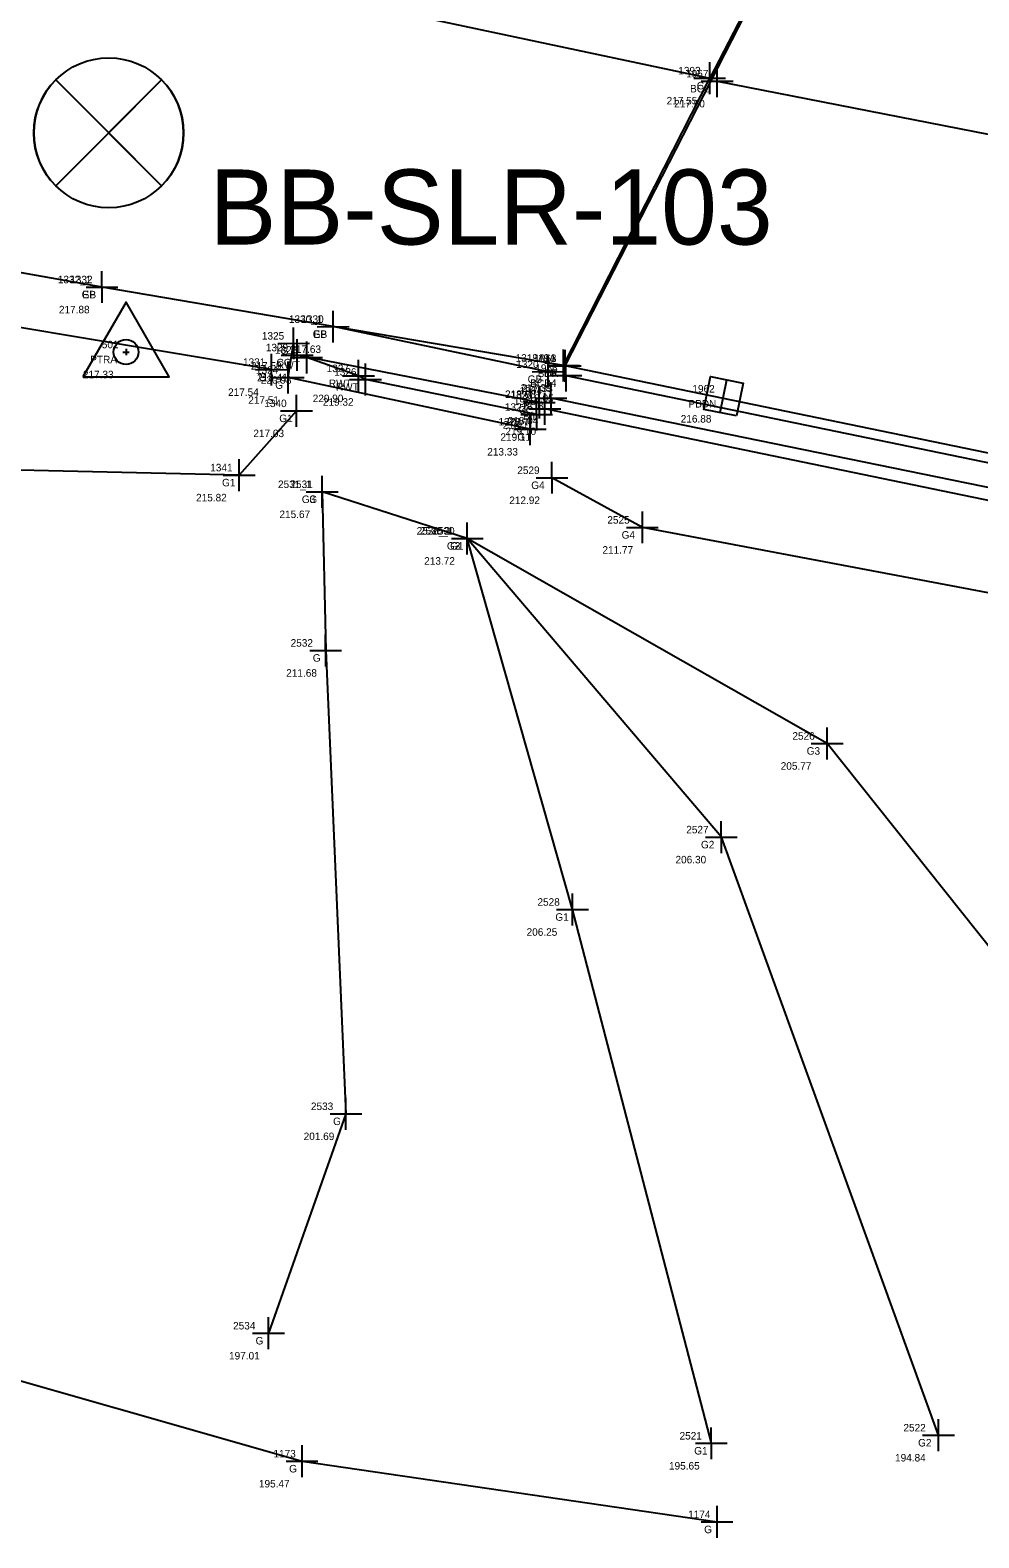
# Model space of a CAD drawing. Extents: x 1155460 to 1157069, y 590691 to 591363.
# Drawn here: x 1156288 to 1156326, y 591043.2 to 591103.4 of the extents above; entities that cross this region are included whole.
import ezdxf

# ---------------------------------------------------------------- set-up
doc = ezdxf.new("R2010")
doc.units = 0
for name, color, linetype in [('Default', 7, 'Continuous'), ('S_BoringLocation_AsDrilled', 7, 'Continuous'), ('S_Bridge_Centerline', 7, 'Continuous'), ('S_Bridge_Curb', 7, 'Continuous'), ('S_Bridge_Deck', 7, 'Continuous'), ('S_Bridge_Downspout', 7, 'Continuous'), ('S_Bridge_Rail', 7, 'Continuous'), ('S_Control_Traverse_Point', 7, 'Continuous'), ('S_Curb_Type_2', 7, 'Continuous'), ('S_Field_Code', 7, 'Continuous'), ('S_Ground_Elevation', 7, 'Continuous'), ('S_Ground_LevelString', 7, 'Continuous'), ('S_Guardrail_Beam', 7, 'Continuous'), ('S_Point_Elevation', 7, 'Continuous'), ('S_Point_Name', 7, 'Continuous'), ('S_RetWall_Top', 7, 'Continuous'), ('S_Roadway_Centerline', 7, 'Continuous'), ('S_Roadway_Edge_Pavement', 7, 'Continuous'), ('S_Survey_Shot', 7, 'Continuous'), ('S_Text', 7, 'Continuous')]:
    doc.layers.add(name, color=color, linetype=linetype)

msp = doc.modelspace()

# ---------------------------------------------------------------- linework, layer by layer
at = {"layer": 'Default'}
for p, q in [((1156291.176, 591099.304), (1156291.176, 591099.304)), ((1156315.757, 591088.777), (1156315.757, 591088.777))]:
    msp.add_line(p, q, dxfattribs=at)
at = {"layer": 'S_BoringLocation_AsDrilled'}
for p, q in [((1156289.059, 591101.422), (1156293.293, 591097.187)), ((1156289.059, 591097.187), (1156293.293, 591101.422))]:
    msp.add_line(p, q, dxfattribs=at)
for points in [[(1156289.059, 591097.187), (1156291.176, 591099.304), (1156289.059, 591101.422)], [(1156293.293, 591101.422), (1156291.176, 591099.304), (1156293.293, 591097.187)]]:
    msp.add_lwpolyline(points, dxfattribs=at)
msp.add_circle((1156291.176, 591099.304), 2.994, dxfattribs=at)
for start, end in [(135, 225), (315, 45)]:
    msp.add_arc((1156291.176, 591099.304), 2.994, start, end, dxfattribs=at)
at = {"layer": 'S_Bridge_Centerline'}
msp.add_lwpolyline([(1156315.508, 591101.371), (1156372.408, 591090.24), (1156431.554, 591078.114), (1156475.254, 591069.515)], dxfattribs=at)
at = {"layer": 'S_Bridge_Curb'}
for points in [[(1156309.461, 591089.603), (1156368.986, 591077.329), (1156424.735, 591065.932), (1156469.272, 591056.957)], [(1156468.917, 591055.972), (1156425.26, 591064.917), (1156366.557, 591076.907), (1156308.862, 591088.698)]]:
    msp.add_lwpolyline(points, dxfattribs=at)
at = {"layer": 'S_Bridge_Deck'}
msp.add_lwpolyline([(1156321.636, 591113.83), (1156379.075, 591102.191), (1156438.058, 591090.105), (1156481.699, 591081.221), (1156469.523, 591057.135), (1156425.816, 591065.905), (1156367.048, 591078.105), (1156309.431, 591089.995)], close=True, dxfattribs=at)
at = {"layer": 'S_Bridge_Downspout'}
msp.add_line((1156315.626, 591088.124), (1156315.888, 591089.431), dxfattribs=at)
msp.add_lwpolyline([(1156316.28, 591087.993), (1156314.973, 591088.254), (1156315.234, 591089.562), (1156316.541, 591089.3)], close=True, dxfattribs=at)
at = {"layer": 'S_Bridge_Rail'}
msp.add_lwpolyline([(1156468.705, 591055.401), (1156424.96, 591064.338), (1156366.256, 591076.365), (1156308.616, 591088.276)], dxfattribs=at)
at = {"layer": 'S_Control_Traverse_Point'}
for p, q in [((1156291.744, 591090.546), (1156291.994, 591090.546)), ((1156291.869, 591090.67), (1156291.869, 591090.421))]:
    msp.add_line(p, q, dxfattribs=at)
msp.add_lwpolyline([(1156290.14, 591089.548), (1156293.598, 591089.548), (1156291.869, 591092.542)], close=True, dxfattribs=at)
msp.add_circle((1156291.869, 591090.546), 0.499, dxfattribs=at)
at = {"layer": 'S_Curb_Type_2'}
msp.add_lwpolyline([(1156308.396, 591088.531), (1156298.714, 591090.424)], dxfattribs=at)
at = {"layer": 'S_Ground_Elevation'}
for points in [[(1156297.688, 591089.841), (1156262.191, 591095.758), (1156236.062, 591101.394), (1156225.846, 591104.279)], [(1156298.682, 591088.195), (1156296.392, 591085.627), (1156279.978, 591085.999), (1156263.481, 591092.536), (1156249.725, 591093.66), (1156229.629, 591098.08), (1156224.845, 591100.347), (1156224.904, 591103.352)], [(1156175.788, 591102.575), (1156176.723, 591093.187), (1156183.705, 591081.742), (1156199.952, 591071.527), (1156234.308, 591066.18), (1156269.105, 591054.717), (1156298.907, 591046.22), (1156315.501, 591043.792)], [(1156308.034, 591087.459), (1156298.35, 591089.525), (1156298.572, 591090.892)], [(1156353.701, 591075.748), (1156312.515, 591083.537), (1156308.901, 591085.521)], [(1156299.714, 591084.96), (1156299.852, 591078.62), (1156300.662, 591060.102), (1156297.566, 591051.334)], [(1156336.683, 591053.85), (1156319.901, 591074.903), (1156305.515, 591083.097), (1156299.714, 591084.96)], [(1156315.273, 591046.935), (1156309.721, 591068.267), (1156305.515, 591083.097)], [(1156324.355, 591047.258), (1156315.673, 591071.16), (1156305.515, 591083.097)]]:
    msp.add_lwpolyline(points, dxfattribs=at)
at = {"layer": 'S_Ground_LevelString'}
msp.add_line((1156309.359, 591090.009), (1156309.359, 591090.009), dxfattribs=at)
for points in [[(1156321.612, 591113.838), (1156315.209, 591101.49)], [(1156309.359, 591090.009), (1156315.209, 591101.49)]]:
    msp.add_lwpolyline(points, dxfattribs=at)
at = {"layer": 'S_Guardrail_Beam'}
msp.add_lwpolyline([(1156308.743, 591089.76), (1156300.149, 591091.559), (1156290.91, 591093.141), (1156262.028, 591098.261), (1156236.884, 591103.703), (1156225.66, 591106.566), (1156223.814, 591107.26), (1156215.406, 591108.888)], dxfattribs=at)
at = {"layer": 'S_RetWall_Top'}
msp.add_lwpolyline([(1156308.287, 591088.047), (1156301.448, 591089.449), (1156301.165, 591089.592), (1156299.094, 591090.328)], dxfattribs=at)
at = {"layer": 'S_Roadway_Centerline'}
msp.add_lwpolyline([(1156220.901, 591120.629), (1156254.128, 591114.222), (1156297.601, 591105.231), (1156315.209, 591101.49)], dxfattribs=at)
at = {"layer": 'S_Roadway_Edge_Pavement'}
msp.add_lwpolyline([(1156309.359, 591090.009), (1156300.149, 591091.559), (1156290.91, 591093.141), (1156262.028, 591098.261), (1156236.884, 591103.703), (1156225.66, 591106.566), (1156223.814, 591107.26), (1156215.252, 591109.143)], dxfattribs=at)
at = {"layer": 'S_Survey_Shot'}
for p, q in [((1156315.21, 591100.854), (1156315.207, 591102.127)), ((1156315.51, 591100.735), (1156315.507, 591102.008)), ((1156314.573, 591101.489), (1156315.845, 591101.492)), ((1156314.872, 591101.37), (1156316.145, 591101.373)), ((1156315.209, 591101.49), (1156315.209, 591101.49)), ((1156315.508, 591101.371), (1156315.508, 591101.371)), ((1156290.911, 591092.505), (1156290.908, 591093.777)), ((1156290.911, 591092.505), (1156290.908, 591093.777)), ((1156290.274, 591093.14), (1156291.546, 591093.142)), ((1156290.274, 591093.14), (1156291.546, 591093.142)), ((1156290.91, 591093.141), (1156290.91, 591093.141)), ((1156290.91, 591093.141), (1156290.91, 591093.141)), ((1156300.15, 591090.922), (1156300.147, 591092.195)), ((1156300.15, 591090.922), (1156300.147, 591092.195)), ((1156298.573, 591090.255), (1156298.57, 591091.528)), ((1156299.512, 591091.557), (1156300.785, 591091.56)), ((1156299.512, 591091.557), (1156300.785, 591091.56)), ((1156300.149, 591091.559), (1156300.149, 591091.559)), ((1156300.149, 591091.559), (1156300.149, 591091.559)), ((1156297.935, 591090.89), (1156299.208, 591090.893)), ((1156298.572, 591090.892), (1156298.572, 591090.892)), ((1156298.715, 591089.788), (1156298.712, 591091.06)), ((1156299.095, 591089.692), (1156299.093, 591090.964)), ((1156297.689, 591089.205), (1156297.687, 591090.477)), ((1156298.078, 591090.423), (1156299.35, 591090.425)), ((1156298.352, 591088.889), (1156298.349, 591090.162)), ((1156298.458, 591090.327), (1156299.73, 591090.329)), ((1156298.714, 591090.424), (1156298.714, 591090.424)), ((1156299.094, 591090.328), (1156299.094, 591090.328)), ((1156301.167, 591088.956), (1156301.164, 591090.228)), ((1156308.744, 591089.124), (1156308.742, 591090.396)), ((1156309.36, 591089.373), (1156309.358, 591090.645)), ((1156309.36, 591089.373), (1156309.358, 591090.645)), ((1156309.432, 591089.358), (1156309.429, 591090.631)), ((1156309.463, 591088.966), (1156309.46, 591090.239)), ((1156297.052, 591089.84), (1156298.324, 591089.843)), ((1156297.688, 591089.841), (1156297.688, 591089.841)), ((1156297.714, 591089.524), (1156298.986, 591089.527)), ((1156298.35, 591089.525), (1156298.35, 591089.525)), ((1156300.529, 591089.59), (1156301.802, 591089.593)), ((1156301.165, 591089.592), (1156301.165, 591089.592)), ((1156301.449, 591088.813), (1156301.446, 591090.085)), ((1156308.107, 591089.759), (1156309.379, 591089.761)), ((1156308.723, 591090.007), (1156309.995, 591090.01)), ((1156308.723, 591090.007), (1156309.995, 591090.01)), ((1156308.743, 591089.76), (1156308.743, 591089.76)), ((1156308.794, 591089.993), (1156310.067, 591089.996)), ((1156308.825, 591089.601), (1156310.098, 591089.604)), ((1156309.359, 591090.009), (1156309.359, 591090.009)), ((1156309.359, 591090.009), (1156309.359, 591090.009)), ((1156309.431, 591089.995), (1156309.431, 591089.995)), ((1156309.461, 591089.603), (1156309.461, 591089.603)), ((1156300.811, 591089.448), (1156302.084, 591089.45)), ((1156301.448, 591089.449), (1156301.448, 591089.449)), ((1156308.397, 591087.895), (1156308.394, 591089.167)), ((1156308.617, 591087.639), (1156308.614, 591088.912)), ((1156308.864, 591088.061), (1156308.861, 591089.334)), ((1156298.684, 591087.558), (1156298.681, 591088.831)), ((1156307.76, 591088.53), (1156309.032, 591088.532)), ((1156308.226, 591088.696), (1156309.498, 591088.699)), ((1156308.289, 591087.411), (1156308.286, 591088.684)), ((1156308.396, 591088.531), (1156308.396, 591088.531)), ((1156308.862, 591088.698), (1156308.862, 591088.698)), ((1156298.046, 591088.193), (1156299.319, 591088.196)), ((1156298.682, 591088.195), (1156298.682, 591088.195)), ((1156307.651, 591088.046), (1156308.924, 591088.049)), ((1156307.979, 591088.274), (1156309.252, 591088.277)), ((1156308.035, 591086.823), (1156308.033, 591088.096)), ((1156308.287, 591088.047), (1156308.287, 591088.047)), ((1156308.616, 591088.276), (1156308.616, 591088.276)), ((1156307.398, 591087.458), (1156308.67, 591087.461)), ((1156308.034, 591087.459), (1156308.034, 591087.459)), ((1156296.393, 591084.991), (1156296.39, 591086.263)), ((1156308.902, 591084.885), (1156308.899, 591086.157)), ((1156295.755, 591085.625), (1156297.028, 591085.628)), ((1156296.392, 591085.627), (1156296.392, 591085.627)), ((1156299.715, 591084.324), (1156299.713, 591085.597)), ((1156299.715, 591084.324), (1156299.713, 591085.597)), ((1156308.264, 591085.519), (1156309.537, 591085.522)), ((1156308.901, 591085.521), (1156308.901, 591085.521)), ((1156299.078, 591084.959), (1156300.35, 591084.962)), ((1156299.078, 591084.959), (1156300.35, 591084.962)), ((1156299.714, 591084.96), (1156299.714, 591084.96)), ((1156299.714, 591084.96), (1156299.714, 591084.96)), ((1156312.516, 591082.901), (1156312.514, 591084.173)), ((1156305.516, 591082.46), (1156305.514, 591083.733)), ((1156305.516, 591082.46), (1156305.514, 591083.733)), ((1156305.516, 591082.46), (1156305.514, 591083.733)), ((1156311.879, 591083.536), (1156313.151, 591083.538)), ((1156312.515, 591083.537), (1156312.515, 591083.537)), ((1156304.879, 591083.095), (1156306.151, 591083.098)), ((1156304.879, 591083.095), (1156306.151, 591083.098)), ((1156304.879, 591083.095), (1156306.151, 591083.098)), ((1156305.515, 591083.097), (1156305.515, 591083.097)), ((1156305.515, 591083.097), (1156305.515, 591083.097)), ((1156305.515, 591083.097), (1156305.515, 591083.097)), ((1156299.854, 591077.984), (1156299.851, 591079.256)), ((1156299.216, 591078.619), (1156300.488, 591078.622)), ((1156299.852, 591078.62), (1156299.852, 591078.62)), ((1156319.903, 591074.267), (1156319.9, 591075.539)), ((1156319.265, 591074.902), (1156320.538, 591074.904)), ((1156319.901, 591074.903), (1156319.901, 591074.903)), ((1156315.674, 591070.524), (1156315.671, 591071.796)), ((1156315.037, 591071.159), (1156316.309, 591071.162)), ((1156315.673, 591071.16), (1156315.673, 591071.16)), ((1156309.722, 591067.631), (1156309.72, 591068.903)), ((1156309.085, 591068.265), (1156310.357, 591068.268)), ((1156309.721, 591068.267), (1156309.721, 591068.267)), ((1156300.664, 591059.466), (1156300.661, 591060.739)), ((1156300.026, 591060.101), (1156301.299, 591060.104)), ((1156300.662, 591060.102), (1156300.662, 591060.102)), ((1156297.567, 591050.698), (1156297.564, 591051.971)), ((1156296.929, 591051.333), (1156298.202, 591051.336)), ((1156297.566, 591051.334), (1156297.566, 591051.334)), ((1156315.274, 591046.299), (1156315.271, 591047.571)), ((1156324.356, 591046.622), (1156324.353, 591047.895)), ((1156298.908, 591045.584), (1156298.906, 591046.856)), ((1156314.637, 591046.934), (1156315.909, 591046.936)), ((1156315.273, 591046.935), (1156315.273, 591046.935)), ((1156323.718, 591047.257), (1156324.991, 591047.26)), ((1156324.355, 591047.258), (1156324.355, 591047.258)), ((1156298.271, 591046.219), (1156299.543, 591046.221)), ((1156298.907, 591046.22), (1156298.907, 591046.22)), ((1156315.503, 591043.156), (1156315.5, 591044.429)), ((1156314.865, 591043.791), (1156316.138, 591043.794)), ((1156315.501, 591043.792), (1156315.501, 591043.792))]:
    msp.add_line(p, q, dxfattribs=at)

# ---------------------------------------------------------------- texts
at = {"layer": 'S_Field_Code'}
for s, p in [('BCL', (1156314.422, 591100.921)), ('C', (1156314.694, 591101.041)), ('GB', (1156290.095, 591092.691)), ('EP', (1156290.123, 591092.691)), ('GB', (1156299.334, 591091.109)), ('EP', (1156299.362, 591091.109)), ('G', (1156298.057, 591090.442)), ('PTRA', (1156290.438, 591090.096)), ('CC', (1156297.885, 591089.974)), ('RWT', (1156297.908, 591089.878)), ('G', (1156297.173, 591089.391)), ('GB', (1156307.928, 591089.31)), ('BDK', (1156308.33, 591089.545)), ('EP', (1156308.572, 591089.559)), ('L1', (1156308.716, 591089.559)), ('G', (1156297.835, 591089.075)), ('RWT', (1156299.98, 591089.142)), ('RWT', (1156300.262, 591088.999)), ('BCB4', (1156308.032, 591089.153)), ('CC', (1156307.567, 591088.081)), ('BCB', (1156307.747, 591088.248)), ('PBDN', (1156314.356, 591088.327)), ('G1', (1156297.997, 591087.745)), ('RWT', (1156307.102, 591087.597)), ('BIL', (1156307.744, 591087.826)), ('G', (1156307.519, 591087.009)), ('G1', (1156295.707, 591085.177)), ('G4', (1156308.072, 591085.071)), ('G3', (1156298.899, 591084.51)), ('G', (1156299.199, 591084.51)), ('G2', (1156304.7, 591082.647)), ('G3', (1156304.7, 591082.647)), ('G1', (1156304.83, 591082.647)), ('G4', (1156311.686, 591083.087)), ('G', (1156299.337, 591078.17)), ('G3', (1156319.086, 591074.453)), ('G2', (1156314.858, 591070.71)), ('G1', (1156309.036, 591067.817)), ('G', (1156300.148, 591059.652)), ('G', (1156297.051, 591050.884)), ('G1', (1156314.588, 591046.485)), ('G2', (1156323.54, 591046.808)), ('G', (1156298.392, 591045.77)), ('G', (1156314.986, 591043.342))]:
    msp.add_text(s, height=0.3, dxfattribs=at).set_placement(p)
at = {"layer": 'S_Point_Elevation'}
for s, p in [('217.55', (1156313.485, 591100.44)), ('217.50', (1156313.787, 591100.321)), ('217.88', (1156289.186, 591092.091)), ('217.88', (1156289.186, 591092.091)), ('217.63', (1156298.439, 591090.509)), ('217.63', (1156298.439, 591090.509)), ('217.59', (1156296.862, 591089.842)), ('217.33', (1156290.145, 591089.496)), ('218.41', (1156297.108, 591089.374)), ('220.93', (1156297.259, 591089.278)), ('217.54', (1156295.95, 591088.791)), ('218.08', (1156307.023, 591088.71)), ('217.39', (1156307.649, 591088.959)), ('217.39', (1156307.649, 591088.959)), ('217.33', (1156307.707, 591088.945)), ('217.51', (1156296.756, 591088.475)), ('220.90', (1156299.333, 591088.542)), ('219.32', (1156299.74, 591088.399)), ('218.05', (1156307.742, 591088.553)), ('218.11', (1156306.934, 591087.481)), ('218.04', (1156307.129, 591087.648)), ('216.88', (1156314.049, 591087.727)), ('217.03', (1156296.961, 591087.145)), ('219.11', (1156306.84, 591086.997)), ('219.10', (1156307.04, 591087.226)), ('213.33', (1156306.312, 591086.409)), ('215.82', (1156294.67, 591084.577)), ('212.92', (1156307.193, 591084.471)), ('215.67', (1156298.004, 591083.91)), ('215.67', (1156298.004, 591083.91)), ('213.72', (1156303.791, 591082.047)), ('213.72', (1156303.791, 591082.047)), ('213.72', (1156303.791, 591082.047)), ('211.77', (1156310.919, 591082.487)), ('211.68', (1156298.275, 591077.57)), ('205.77', (1156318.047, 591073.853)), ('206.30', (1156313.84, 591070.11)), ('206.25', (1156307.886, 591067.217)), ('201.69', (1156298.971, 591059.052)), ('197.01', (1156295.988, 591050.284)), ('195.65', (1156313.579, 591045.885)), ('194.84', (1156322.619, 591046.208)), ('195.47', (1156297.183, 591045.17))]:
    msp.add_text(s, height=0.3, dxfattribs=at).set_placement(p)
at = {"layer": 'S_Point_Name'}
for s, p in [('1393', (1156313.952, 591101.64)), ('1967', (1156314.264, 591101.521)), ('1332_1', (1156289.141, 591093.291)), ('1332', (1156289.639, 591093.291)), ('1330_1', (1156298.382, 591091.709)), ('1330', (1156298.88, 591091.709)), ('1325', (1156297.301, 591091.042)), ('501', (1156290.901, 591090.696)), ('1329', (1156297.457, 591090.574)), ('1328', (1156297.823, 591090.478)), ('1331', (1156296.547, 591089.991)), ('1319A_1', (1156307.448, 591090.159)), ('1320', (1156307.474, 591089.91)), ('1319A', (1156307.902, 591090.159)), ('1963', (1156308.188, 591090.145)), ('1324', (1156297.065, 591089.675)), ('1327', (1156299.892, 591089.742)), ('1326', (1156300.191, 591089.599)), ('1966', (1156308.233, 591089.753)), ('1321', (1156307.255, 591088.681)), ('1964', (1156307.606, 591088.848)), ('1962', (1156314.515, 591088.927)), ('1340', (1156297.4, 591088.345)), ('1322', (1156307.017, 591088.197)), ('1965', (1156307.373, 591088.426)), ('1323', (1156306.763, 591087.609)), ('1341', (1156295.237, 591085.777)), ('2529', (1156307.514, 591085.671)), ('2531_1', (1156297.945, 591085.11)), ('2531', (1156298.443, 591085.11)), ('2530_2', (1156303.488, 591083.247)), ('2530_1', (1156303.618, 591083.247)), ('2530', (1156304.116, 591083.247)), ('2525', (1156311.114, 591083.687)), ('2532', (1156298.451, 591078.77)), ('2526', (1156318.515, 591075.053)), ('2527', (1156314.27, 591071.31)), ('2528', (1156308.32, 591068.417)), ('2533', (1156299.262, 591060.252)), ('2534', (1156296.151, 591051.484)), ('2521', (1156314.002, 591047.085)), ('2522', (1156322.954, 591047.408)), ('1173', (1156297.764, 591046.37)), ('1174', (1156314.344, 591043.943))]:
    msp.add_text(s, height=0.3, dxfattribs=at).set_placement(p)
at = {"layer": 'S_Text'}
msp.add_text('BB-SLR-103', height=3, dxfattribs=at).set_placement((1156295.206, 591094.84))

doc.saveas('drawing.dxf')
